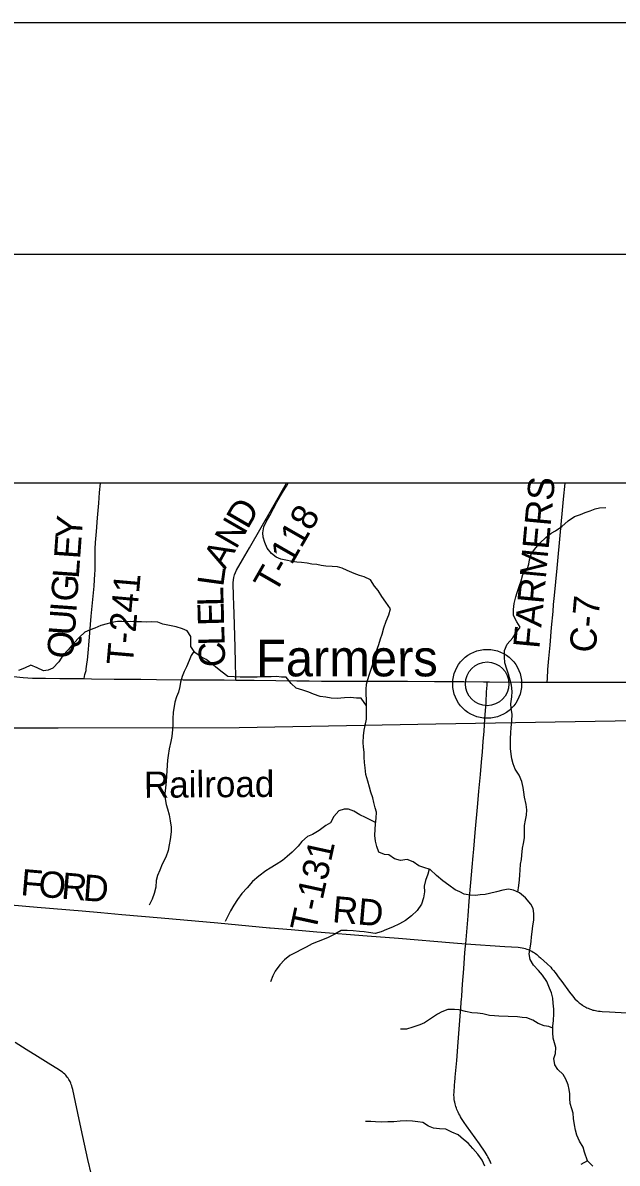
# Model space of a CAD drawing. Extents: x 0 to 1052, y -194 to 246.
# Drawn here: x 3.805 to 5.091, y 19.536 to 22 of the extents above; entities that cross this region are included whole.
import ezdxf

# ---------------------------------------------------------------- set-up
doc = ezdxf.new("R2010")
doc.units = 0
for name, color, linetype in [('GM_X_Corporation', 7, 'Continuous'), ('GM_X_County_Road', 7, 'Continuous'), ('GM_X_County_Road_Text', 7, 'Continuous'), ('GM_X_Major_River', 7, 'Continuous'), ('GM_X_Minor_River', 7, 'Continuous'), ('GM_X_Rail_Line', 7, 'Continuous'), ('GM_X_Rail_Line_Text', 7, 'Continuous'), ('GM_X_State_Route', 7, 'Continuous'), ('GM_X_Township_Road', 7, 'Continuous'), ('GM_X_Township_Road_Text', 7, 'Continuous'), ('GM_X_Unincorporated', 7, 'Continuous'), ('GM_X_Unincorporated_Location', 7, 'Continuous'), ('GM_X_Unincorporated_Text', 7, 'Continuous'), ('SH_Border', 7, 'Continuous'), ('SH_Cut_Line', 7, 'Continuous')]:
    doc.layers.add(name, color=color, linetype=linetype)

msp = doc.modelspace()

# ---------------------------------------------------------------- linework, layer by layer
at = {"layer": 'GM_X_Corporation'}
for points in [[(5.1788, 17.6981), (5.491, 17.9457), (6.1888, 18.4644), (6.5994, 18.7694), (6.8785, 18.9763), (8.1871, 19.9814), (8.6571, 20.341), (8.7822, 20.435), (8.7822, 21.0055), (1.9822, 21.0055), (1.9822, 14.2055)], [(5.1788, 17.6981), (5.491, 17.9457), (6.1888, 18.4644), (6.152, 18.6129), (5.992, 19.3448), (5.9283, 19.6076), (5.6935, 20.5776), (5.5898, 21.0055), (1.9822, 21.0055), (1.9822, 14.2055)]]:
    msp.add_lwpolyline(points, dxfattribs=at)
at = {"layer": 'GM_X_County_Road'}
for points in [[(4.9393, 20.575), (4.9398, 20.583), (4.9411, 20.6028), (4.9431, 20.6263), (4.9458, 20.6554), (4.949, 20.6932), (4.9521, 20.7278), (4.9533, 20.7427), (4.955, 20.7625), (4.9607, 20.8218), (4.975, 20.9709), (4.9784, 21.0055)], [(4.7633, 20.0099), (4.7682, 20.07), (4.7709, 20.1021), (4.7745, 20.1423), (4.7772, 20.1752), (4.7795, 20.1998), (4.7808, 20.2147), (4.7838, 20.25), (4.7897, 20.3131), (4.7919, 20.3397), (4.7954, 20.3755), (4.7976, 20.4022), (4.7994, 20.4245), (4.8013, 20.4467), (4.8028, 20.4691), (4.8049, 20.4963), (4.8071, 20.5316), (4.8083, 20.554), (4.8093, 20.5688), (4.8098, 20.5761)], [(4.8098, 20.5761), (4.8145, 20.576), (4.8816, 20.5752), (4.8934, 20.5752), (4.9188, 20.5752), (4.9393, 20.575)], [(4.8181, 19.5347), (4.8168, 19.5378), (4.816, 19.5399), (4.8143, 19.5434), (4.813, 19.5462), (4.8111, 19.5496), (4.8094, 19.5527), (4.8051, 19.5596), (4.7927, 19.5775), (4.7648, 19.6164), (4.7597, 19.6238), (4.7567, 19.6281), (4.7542, 19.6323), (4.7519, 19.636), (4.7502, 19.6392), (4.7484, 19.6425), (4.7468, 19.646), (4.7453, 19.6492), (4.7441, 19.6521), (4.743, 19.655), (4.7421, 19.6581), (4.7412, 19.6608), (4.7404, 19.664), (4.7396, 19.6674), (4.7391, 19.6701), (4.7385, 19.6734), (4.7382, 19.6767), (4.7379, 19.6795), (4.7378, 19.6823), (4.7377, 19.685), (4.7379, 19.6881), (4.738, 19.6906), (4.7398, 19.7134), (4.7402, 19.7174), (4.7406, 19.7215), (4.7438, 19.7574), (4.7468, 19.797), (4.7527, 19.8725), (4.7544, 19.8913), (4.7546, 19.8942), (4.7548, 19.8975), (4.7565, 19.9227), (4.7591, 19.9555), (4.7616, 19.9908), (4.7629, 20.005), (4.7633, 20.0099)]]:
    msp.add_lwpolyline(points, dxfattribs=at)
at = {"layer": 'GM_X_Major_River'}
msp.add_lwpolyline([(5.0383, 19.529), (5.0268, 19.541), (5.0125, 19.5326)], dxfattribs=at)
at = {"layer": 'GM_X_Minor_River'}
for points in [[(4.5489, 20.524), (4.5487, 20.5373), (4.5481, 20.5494), (4.5478, 20.5597), (4.5487, 20.5707), (4.5515, 20.5809), (4.5551, 20.5922), (4.5587, 20.6032), (4.563, 20.616), (4.5658, 20.6262), (4.5698, 20.641), (4.5753, 20.6569), (4.5789, 20.6686), (4.5825, 20.6792), (4.5864, 20.6928), (4.5908, 20.7072), (4.5967, 20.7204), (4.6007, 20.734), (4.5906, 20.7478), (4.582, 20.7604), (4.5738, 20.7734), (4.566, 20.783), (4.5574, 20.7964), (4.5435, 20.8027), (4.5336, 20.8054), (4.5219, 20.8102), (4.5068, 20.8164), (4.4962, 20.8219), (4.4856, 20.8247), (4.4746, 20.8252), (4.461, 20.8258), (4.4507, 20.827), (4.4409, 20.8294), (4.4303, 20.8303), (4.4204, 20.832), (4.4079, 20.834), (4.398, 20.8345), (4.3878, 20.8358), (4.3738, 20.839), (4.3632, 20.8411), (4.3534, 20.8454), (4.3432, 20.8531), (4.3339, 20.8646), (4.3287, 20.8772), (4.3254, 20.8882), (4.3244, 20.8977), (4.3265, 20.911), (4.3316, 20.9219), (4.3394, 20.9355), (4.3475, 20.9502), (4.3546, 20.9642), (4.3623, 20.9777), (4.3689, 20.9887), (4.3755, 20.9988), (4.3793, 21.0055)], [(4.8759, 20.1217), (4.8784, 20.1355), (4.8797, 20.1484), (4.8802, 20.159), (4.8811, 20.1693), (4.882, 20.1818), (4.8837, 20.192), (4.8845, 20.2015), (4.8863, 20.2167), (4.8883, 20.2265), (4.8904, 20.239), (4.8901, 20.2515), (4.8903, 20.2652), (4.8924, 20.2769), (4.8944, 20.2879), (4.8953, 20.2993), (4.8943, 20.3111), (4.8904, 20.3267), (4.889, 20.3377), (4.8876, 20.3476), (4.8847, 20.3606), (4.8788, 20.3739), (4.8703, 20.3869), (4.8655, 20.3984), (4.863, 20.4098), (4.8612, 20.4197), (4.8599, 20.4322), (4.8601, 20.4531), (4.8611, 20.4668), (4.8616, 20.4766), (4.8633, 20.4914), (4.8635, 20.5055), (4.8618, 20.5188), (4.8611, 20.5287), (4.8632, 20.5438), (4.8634, 20.5548), (4.8621, 20.5685), (4.8592, 20.5795), (4.8555, 20.5925), (4.8519, 20.6032), (4.8475, 20.6169), (4.8469, 20.6302), (4.8471, 20.6435), (4.8526, 20.6571), (4.8649, 20.671), (4.8719, 20.6811), (4.8808, 20.6939), (4.8741, 20.7058), (4.8663, 20.7195), (4.8669, 20.7324), (4.8682, 20.7453), (4.8718, 20.7593), (4.8746, 20.7691), (4.8786, 20.7816), (4.8833, 20.7941), (4.8865, 20.8077), (4.8965, 20.8186), (4.8997, 20.8299), (4.901, 20.8394), (4.9057, 20.853), (4.915, 20.8654), (4.9235, 20.8756), (4.9362, 20.8879), (4.9477, 20.8973), (4.9573, 20.9025), (4.9714, 20.9114), (4.9849, 20.9241), (4.9983, 20.933), (5.0117, 20.9374), (5.0216, 20.9419), (5.0327, 20.9455), (5.043, 20.9496), (5.0525, 20.9521), (5.0662, 20.953)], [(4.5489, 20.524), (4.5373, 20.5404), (4.5271, 20.5409), (4.5138, 20.5419), (4.5009, 20.5417), (4.4849, 20.5396), (4.472, 20.5405), (4.461, 20.5429), (4.4481, 20.5439), (4.4337, 20.5494), (4.4239, 20.5533), (4.4107, 20.558), (4.3967, 20.5624), (4.3854, 20.5724), (4.375, 20.5858), (4.3647, 20.5863), (4.3537, 20.5872), (4.3427, 20.587), (4.3321, 20.5864), (4.3222, 20.5865), (4.3119, 20.5859), (4.2986, 20.586), (4.2861, 20.5858), (4.2755, 20.586), (4.2622, 20.5865), (4.2489, 20.5878), (4.2361, 20.5967), (4.2263, 20.6048), (4.2139, 20.6145), (4.2019, 20.6241), (4.1917, 20.6292), (4.177, 20.6392), (4.1689, 20.6523), (4.1686, 20.664), (4.1684, 20.6739), (4.1606, 20.6858), (4.1507, 20.6905), (4.1368, 20.6948), (4.119, 20.6985), (4.108, 20.7005), (4.097, 20.7048), (4.0833, 20.7054), (4.0731, 20.7051), (4.0621, 20.7053), (4.0499, 20.7058), (4.0389, 20.706), (4.029, 20.7057), (4.0192, 20.7066), (4.0097, 20.7063), (3.9975, 20.7042), (3.9876, 20.7013), (3.9738, 20.6977), (3.9609, 20.6922), (3.9509, 20.6885), (3.9391, 20.683), (3.9276, 20.6725), (3.9152, 20.6586), (3.9033, 20.6451), (3.8921, 20.6327), (3.8828, 20.6191), (3.8701, 20.6053), (3.8601, 20.6008), (3.8499, 20.5995), (3.8359, 20.6065), (3.8223, 20.6116), (3.8085, 20.6053), (3.7956, 20.6005)], [(4.1754, 20.6418), (4.1697, 20.6329), (4.165, 20.6223), (4.1592, 20.6084), (4.1541, 20.5985), (4.1498, 20.5872), (4.1462, 20.5751), (4.1449, 20.5656), (4.1421, 20.5539), (4.1374, 20.5437), (4.1342, 20.532), (4.1301, 20.51), (4.1296, 20.4964), (4.1298, 20.4838), (4.1289, 20.4732), (4.1272, 20.4581), (4.1255, 20.4467), (4.1219, 20.4312), (4.1194, 20.4168), (4.1185, 20.4069), (4.1176, 20.3959), (4.1167, 20.3838), (4.1162, 20.3728), (4.1152, 20.3603), (4.1135, 20.3466), (4.1126, 20.3345), (4.1132, 20.3231), (4.1153, 20.3109), (4.1179, 20.3014), (4.1215, 20.2888), (4.124, 20.2755), (4.1261, 20.2622), (4.1263, 20.2516), (4.1242, 20.2353), (4.1218, 20.2239), (4.1197, 20.2114), (4.1146, 20.1974), (4.1064, 20.182), (4.1017, 20.1691), (4.0962, 20.1571), (4.0938, 20.1468), (4.0932, 20.1324), (4.0892, 20.1184), (4.0853, 20.1063), (4.0786, 20.0931)], [(5.0268, 19.541), (5.0204, 19.5597), (5.0171, 19.5704), (5.0093, 19.5834), (5.0038, 19.5964), (5.0009, 19.6074), (4.9988, 19.6185), (4.9967, 19.6321), (4.9953, 19.6436), (4.9928, 19.6531), (4.9888, 19.6649), (4.9885, 19.6759), (4.9883, 19.6854), (4.9873, 19.6953), (4.9847, 19.7048), (4.9796, 19.717), (4.974, 19.7273), (4.9628, 19.7385), (4.9561, 19.7481), (4.9536, 19.7618), (4.9572, 19.7731), (4.9581, 19.786), (4.9552, 19.7955), (4.9526, 19.8062), (4.9517, 19.8184), (4.9519, 19.8328), (4.9528, 19.8434), (4.9541, 19.859), (4.9539, 19.8688), (4.9521, 19.8814), (4.9519, 19.8924), (4.949, 19.9042), (4.9446, 19.9141), (4.9387, 19.9282), (4.929, 19.942), (4.9204, 19.952), (4.9095, 19.9635), (4.9025, 19.9762), (4.9007, 19.9883), (4.9032, 20.0046), (4.9045, 20.0149), (4.9058, 20.0247), (4.9067, 20.0357), (4.9087, 20.0486), (4.9104, 20.0607), (4.9106, 20.0751), (4.9088, 20.0858), (4.904, 20.0957), (4.8928, 20.1095), (4.8797, 20.12), (4.8668, 20.1258), (4.8558, 20.1279), (4.8433, 20.1254), (4.8296, 20.1221), (4.8147, 20.1185), (4.8052, 20.1164), (4.7942, 20.1154), (4.7846, 20.1143), (4.7725, 20.1149), (4.76, 20.1169), (4.7502, 20.122), (4.7404, 20.1267), (4.7264, 20.1367), (4.714, 20.1456), (4.7001, 20.1572), (4.6862, 20.1703), (4.6723, 20.175), (4.6617, 20.1786), (4.6496, 20.1867), (4.6364, 20.1918), (4.6223, 20.1897), (4.6091, 20.1937), (4.597, 20.2022), (4.5875, 20.2031), (4.5755, 20.2078), (4.5707, 20.22), (4.5682, 20.2314), (4.5668, 20.244), (4.5677, 20.2572), (4.5679, 20.2686), (4.5696, 20.2811), (4.5701, 20.294), (4.5676, 20.3035), (4.5647, 20.315), (4.5622, 20.3253), (4.5582, 20.3378), (4.5553, 20.3481), (4.5517, 20.3615), (4.5469, 20.3759), (4.5456, 20.3904), (4.5442, 20.4014), (4.5436, 20.4132), (4.5434, 20.4238), (4.5424, 20.4345), (4.5414, 20.4447), (4.5423, 20.4595), (4.5436, 20.4713), (4.546, 20.4819), (4.5485, 20.4951), (4.5483, 20.5118), (4.5489, 20.524)], [(4.5684, 20.2722), (4.5581, 20.2767), (4.5464, 20.2826), (4.534, 20.2884), (4.5212, 20.2962), (4.5098, 20.3005), (4.5003, 20.301), (4.4889, 20.2974), (4.4777, 20.285), (4.4707, 20.271), (4.4604, 20.2655), (4.4462, 20.2546), (4.432, 20.2457), (4.4213, 20.242), (4.409, 20.2312), (4.4005, 20.2207), (4.3878, 20.2076), (4.3771, 20.1986), (4.3667, 20.19), (4.3529, 20.1811), (4.3406, 20.1732), (4.3311, 20.1677), (4.3157, 20.1561), (4.3023, 20.1445), (4.2903, 20.131), (4.2792, 20.1186), (4.2695, 20.1055), (4.2617, 20.093), (4.2543, 20.081), (4.2493, 20.0708), (4.2426, 20.058)], [(4.6843, 20.1709), (4.6816, 20.1605), (4.6761, 20.1465), (4.6736, 20.1344), (4.6738, 20.1219), (4.6718, 20.109), (4.6678, 20.0957), (4.6581, 20.0818), (4.6458, 20.0702), (4.6328, 20.0605), (4.6197, 20.0527), (4.6045, 20.0461), (4.5922, 20.0409), (4.58, 20.0354), (4.5671, 20.0321), (4.553, 20.0346), (4.5436, 20.0359), (4.5333, 20.0364), (4.52, 20.0377), (4.5068, 20.0386), (4.4938, 20.0384), (4.4801, 20.031), (4.4659, 20.0236), (4.4533, 20.0184), (4.4438, 20.0148), (4.4312, 20.0096), (4.4178, 20.0026), (4.4078, 19.9978), (4.396, 19.9907), (4.3826, 19.9848), (4.3715, 19.9754), (4.3611, 19.9642), (4.3514, 19.9507), (4.3459, 19.9409), (4.3412, 19.928)], [(4.9518, 19.8279), (4.9427, 19.8314), (4.9329, 19.8323), (4.9196, 19.8378), (4.9083, 19.8447), (4.8951, 19.8502), (4.8856, 19.8507), (4.875, 19.852), (4.8351, 19.8537), (4.8253, 19.8542), (4.8147, 19.8551), (4.8003, 19.8583), (4.7885, 19.86), (4.7764, 19.8609), (4.7627, 19.8637), (4.7487, 19.8669), (4.7389, 19.8678), (4.7248, 19.868), (4.7118, 19.8625), (4.7019, 19.8577), (4.6873, 19.8476), (4.6739, 19.8394), (4.664, 19.835), (4.6491, 19.8295), (4.635, 19.8251), (4.6224, 19.8253)], [(4.8043, 19.5295), (4.7988, 19.5421), (4.7894, 19.5551), (4.7786, 19.5678), (4.7685, 19.5789), (4.7587, 19.587), (4.7471, 19.5974), (4.7331, 19.6025), (4.7199, 19.6092), (4.7062, 19.6101), (4.6933, 19.6114), (4.6827, 19.6157), (4.6703, 19.6235), (4.6597, 19.6255), (4.6483, 19.6264), (4.6343, 19.627), (4.6213, 19.6264), (4.6077, 19.6254), (4.5947, 19.6252), (4.5807, 19.6242), (4.5682, 19.6255), (4.5579, 19.6257), (4.5461, 19.6262)]]:
    msp.add_lwpolyline(points, dxfattribs=at)
at = {"layer": 'GM_X_Rail_Line'}
msp.add_lwpolyline([(1.9822, 20.4716), (2.0551, 20.4708), (2.4106, 20.4737), (3.1102, 20.4767), (3.8818, 20.4767), (4.2729, 20.4769), (4.6986, 20.4854), (5.3445, 20.496), (5.674, 20.5018), (6.3876, 20.5117), (6.862, 20.5208), (7.7527, 20.5376), (8.5619, 20.5538), (8.7822, 20.5583)], dxfattribs=at)
at = {"layer": 'GM_X_State_Route'}
for points in [[(3.785, 20.5872), (3.8061, 20.5854), (3.8164, 20.5848), (3.826, 20.5842), (3.8342, 20.5839), (3.8434, 20.5836), (3.8542, 20.5835), (3.8856, 20.583), (3.9198, 20.583), (3.9376, 20.5828), (3.954, 20.5825), (4.0031, 20.582), (4.0608, 20.5816), (4.0944, 20.5813), (4.1522, 20.5804), (4.1562, 20.5804)], [(4.1562, 20.5804), (4.1913, 20.58), (4.2404, 20.5799), (4.2663, 20.5796), (4.2814, 20.5794), (4.3056, 20.5794), (4.3528, 20.5788), (4.3976, 20.5782), (4.4249, 20.5781), (4.4516, 20.5776), (4.4703, 20.5775), (4.5107, 20.5774), (4.5461, 20.5775), (4.6132, 20.5772), (4.6374, 20.5773), (4.6958, 20.577), (4.7213, 20.577), (4.7592, 20.5766), (4.802, 20.5762), (4.8098, 20.5761)], [(4.8098, 20.5761), (4.8145, 20.576), (4.8816, 20.5752), (4.8934, 20.5752), (4.9188, 20.5752), (4.9393, 20.575)], [(4.9393, 20.575), (4.9406, 20.575), (4.9555, 20.575)], [(4.9555, 20.575), (4.9903, 20.575), (5.0176, 20.5751), (5.0338, 20.5751), (5.0462, 20.5752), (5.063, 20.5755), (5.094, 20.5753), (5.1214, 20.5754), (5.1729, 20.5758), (5.2052, 20.5758), (5.2469, 20.5762), (5.254, 20.5762)], [(3.9537, 19.5107), (3.9461, 19.544), (3.9353, 19.5938), (3.9296, 19.6199), (3.9195, 19.6673), (3.9133, 19.6951), (3.9122, 19.699), (3.9111, 19.7029), (3.91, 19.7061), (3.909, 19.7087), (3.9073, 19.7126), (3.905, 19.7169), (3.9032, 19.7195), (3.9015, 19.7219), (3.898, 19.7261), (3.8958, 19.7282), (3.8933, 19.7303), (3.8907, 19.7326), (3.8878, 19.7346), (3.8846, 19.7368), (3.8789, 19.7405), (3.8657, 19.7486), (3.837, 19.766), (3.8127, 19.7811), (3.7886, 19.7964)]]:
    msp.add_lwpolyline(points, dxfattribs=at)
at = {"layer": 'GM_X_Township_Road'}
for points in [[(3.9376, 20.5828), (3.9397, 20.5915), (3.9419, 20.6006), (3.9426, 20.6047), (3.9432, 20.6085), (3.944, 20.6146), (3.945, 20.6227), (3.9473, 20.6462), (3.9483, 20.6555), (3.9502, 20.6821), (3.9534, 20.718), (3.9592, 20.7829), (3.9612, 20.8096), (3.9616, 20.8165), (3.9619, 20.8226), (3.9619, 20.8267), (3.9619, 20.83), (3.9618, 20.8356), (3.9616, 20.8412), (3.9615, 20.8458), (3.9614, 20.8499), (3.9614, 20.8532), (3.9615, 20.8568), (3.9616, 20.8606), (3.9617, 20.8636), (3.9627, 20.8772), (3.9645, 20.9007), (3.9668, 20.9305), (3.9693, 20.9621), (3.9713, 20.985), (3.973, 21.0055)], [(4.2663, 20.5796), (4.2662, 20.5874), (4.2656, 20.6166), (4.2643, 20.6514), (4.2635, 20.6737), (4.2628, 20.7004), (4.2616, 20.7433), (4.2611, 20.76), (4.2605, 20.7898), (4.2607, 20.796), (4.2615, 20.8016), (4.2629, 20.807), (4.2649, 20.8122), (4.2674, 20.8172), (4.2802, 20.8392), (4.2955, 20.8655), (4.3462, 20.9532), (4.3755, 21.0055)], [(3.076, 20.1549), (3.0822, 20.1545), (3.1382, 20.1508), (3.262, 20.1402), (3.3091, 20.1362), (3.3505, 20.1325), (3.5257, 20.1164), (3.6167, 20.1087), (3.6649, 20.1038), (3.8365, 20.0888), (3.9336, 20.0809), (3.9739, 20.0774), (4.0191, 20.0735), (4.1045, 20.0657), (4.2269, 20.0551), (4.3385, 20.0444), (4.3401, 20.0443)], [(4.3401, 20.0443), (4.3854, 20.0406), (4.4412, 20.0359), (4.55, 20.0272), (4.6176, 20.022), (4.7371, 20.0121), (4.7633, 20.0099)], [(4.7633, 20.0099), (4.8479, 20.0041), (4.877, 20.0023), (4.8812, 20.0019), (4.8852, 20.0014), (4.8888, 20.0006), (4.892, 19.9998), (4.8955, 19.9986), (4.8984, 19.9974), (4.9013, 19.9962), (4.9039, 19.9949), (4.9063, 19.9936), (4.9091, 19.9919), (4.9117, 19.9904), (4.9141, 19.9886), (4.9168, 19.9867), (4.9192, 19.9846), (4.9216, 19.9827), (4.925, 19.9796), (4.9392, 19.9665), (4.9471, 19.9591), (4.9498, 19.956), (4.9528, 19.9523), (4.9564, 19.9476), (4.9656, 19.9359), (4.9708, 19.9283), (4.9878, 19.9053), (4.9944, 19.8971), (4.9996, 19.891), (5.0048, 19.8858), (5.0085, 19.8825), (5.0108, 19.8808), (5.0129, 19.8792), (5.0155, 19.8775), (5.0175, 19.8761), (5.0201, 19.8747), (5.0228, 19.8731), (5.0254, 19.8718), (5.0278, 19.8706), (5.0309, 19.8693), (5.0329, 19.8685), (5.0355, 19.8677), (5.0381, 19.8668), (5.0408, 19.8662), (5.0441, 19.8655), (5.0469, 19.865), (5.0502, 19.8645), (5.0541, 19.8641), (5.0582, 19.8638), (5.0743, 19.8628), (5.1115, 19.8604)]]:
    msp.add_lwpolyline(points, dxfattribs=at)
at = {"layer": 'GM_X_Unincorporated'}
for radius in [0.0744, 0.0472]:
    msp.add_circle((4.8096, 20.5716), radius, dxfattribs=at)
at = {"layer": 'GM_X_Unincorporated_Location'}
msp.add_line((4.8096, 20.5716), (4.8096, 20.5716), dxfattribs=at)
at = {"layer": 'SH_Border'}
msp.add_lwpolyline([(1.5, 21.5), (33.5, 21.5), (33.5, 0.5), (1.5, 0.5)], close=True, dxfattribs=at)
at = {"layer": 'SH_Cut_Line'}
msp.add_lwpolyline([(0, 0), (34, 0), (34, 22), (0, 22)], close=True, dxfattribs=at)

# ---------------------------------------------------------------- texts
at = {"layer": 'GM_X_County_Road_Text'}
for s, rotation, p in [('FARMERS', 84.7126, (4.9224, 20.6464)), ('C-7', 84.9859, (5.0439, 20.6373))]:
    msp.add_text(s, height=0.05682, rotation=rotation, dxfattribs=at).set_placement(p)
at = {"layer": 'GM_X_Rail_Line_Text'}
msp.add_text('Railroad', height=0.05663, rotation=0.4496, dxfattribs=at).set_placement((4.0674, 20.3252))
at = {"layer": 'GM_X_Township_Road_Text'}
for s, height, rotation, p in [('D', 0.0568, 59.994, (4.2915, 20.9038)), ('T-118', 0.05682, 60.1879, (4.3509, 20.7642)), ('Y', 0.0568, 85.6463, (3.9321, 20.8825)), ('N', 0.0568, 59.994, (4.2665, 20.8605)), ('E', 0.0568, 85.9724, (3.9291, 20.8402)), ('A', 0.0568, 61.2596, (4.2427, 20.817)), ('L', 0.0568, 85.9905, (3.9261, 20.7978)), ('G', 0.0568, 85.9877, (3.9226, 20.7479)), ('T-241', 0.05682, 85.0057, (4.0429, 20.6104)), ('L', 0.0568, 82.1978, (4.2386, 20.7801)), ('L', 0.0568, 91.3672, (4.2397, 20.74)), ('U', 0.0568, 85.986, (3.9175, 20.6748)), ('I', 0.0568, 85.9845, (3.921, 20.7247)), ('E', 0.0568, 91.5153, (4.2409, 20.6975)), ('Q', 0.0568, 85.986, (3.914, 20.6249)), ('L', 0.0568, 91.5113, (4.242, 20.655)), ('C', 0.0568, 91.5067, (4.2432, 20.6084)), ('T-131', 0.05682, 77.7706, (4.4386, 20.0329)), ('F', 0.0568, 355.1476, (3.7991, 20.1151)), ('O', 0.0568, 355.1456, (3.8373, 20.1118)), ('R', 0.0568, 355.1465, (3.8871, 20.1076)), ('D', 0.0568, 355.5745, (3.9341, 20.1036)), ('RD', 0.05682, 355.0719, (4.4733, 20.0567))]:
    msp.add_text(s, height=height, rotation=rotation, dxfattribs=at).set_placement(p)
at = {"layer": 'GM_X_Unincorporated_Text'}
msp.add_text('Farmers', height=0.07898, rotation=0, dxfattribs=at).set_placement((4.3097, 20.5878))

doc.saveas('drawing.dxf')
